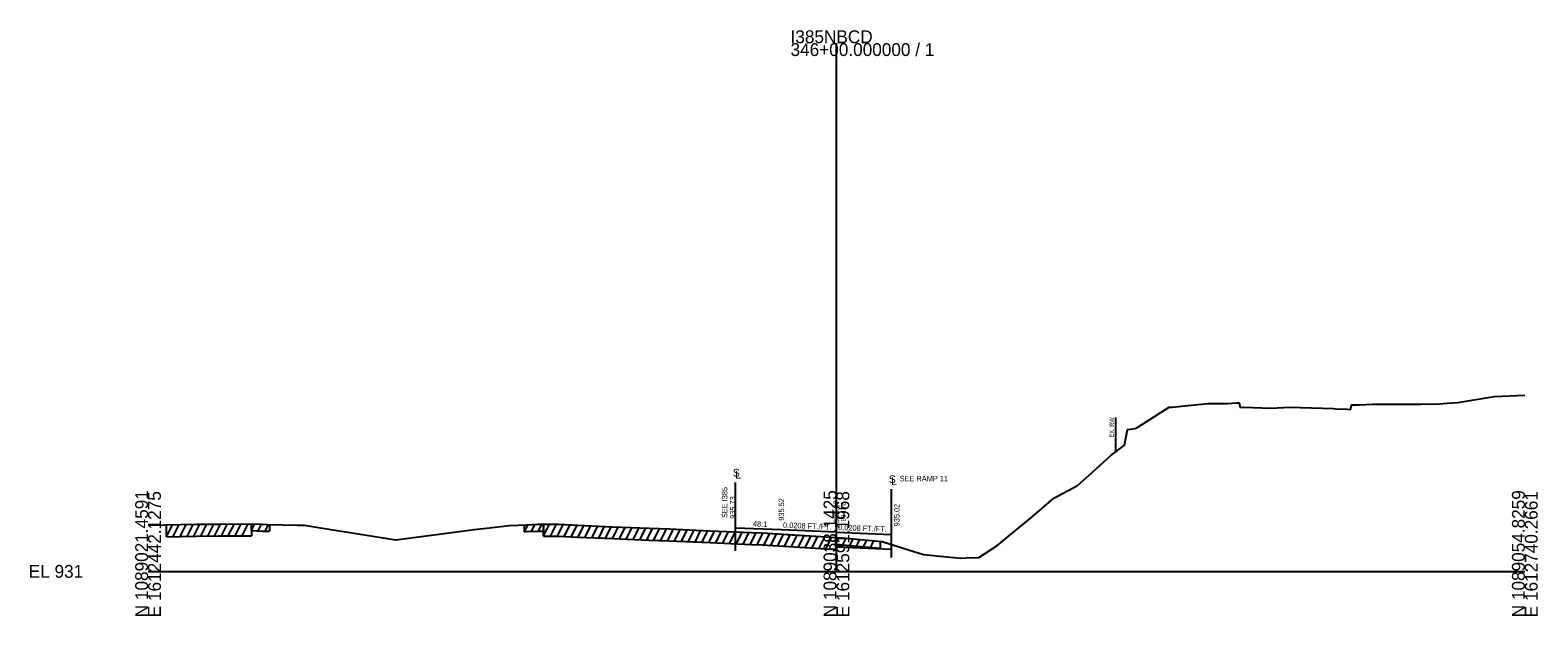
# Model space of a CAD drawing. Extents: x -26 to 1613369, y -10 to 1281970.
# Drawn here: x -25.7 to 302.8, y 16490.3 to 16617.9 of the extents above; entities that cross this region are included whole.
import ezdxf

# ---------------------------------------------------------------- set-up
doc = ezdxf.new("R2010")
doc.units = 0
for name, color, linetype in [('RD_EX_Misc', 7, 'Continuous'), ('RD_GPK_XS_Cell', 7, 'Continuous'), ('RD_Sketch1', 7, 'Continuous'), ('RD_XS_Base', 7, 'Continuous'), ('RD_XS_ExGround', 7, 'Continuous'), ('RD_XS_ExPaveRet', 7, 'Continuous'), ('RD_XS_ExRW', 7, 'Continuous'), ('RD_XS_MatchLine', 7, 'Continuous'), ('RD_XS_Pave', 7, 'Continuous'), ('RD_XS_PaveShd', 7, 'Continuous'), ('RD_XS_TX_Elev_EX', 7, 'Continuous'), ('RD_XS_TX_Elev_PR', 7, 'Continuous'), ('RD_XS_TX_MatchLine', 7, 'Continuous'), ('RD_XS_TX_Notes', 7, 'Continuous'), ('RD_XS_TX_ShdSlope', 7, 'Continuous'), ('RD_XS_TX_Slope', 7, 'Continuous')]:
    doc.layers.add(name, color=color, linetype=linetype)

msp = doc.modelspace()

# ---------------------------------------------------------------- linework, layer by layer
at = {"layer": 'RD_EX_Misc'}
for p, q in [((22.51, 16508.88), (22.51, 16510.38)), ((22.51, 16508.88), (24.87, 16508.78)), ((22.51, 16508.88), (22.51, 16508.88)), ((24.87, 16508.78), (26, 16508.74)), ((26.45, 16510.23), (26.45, 16508.73)), ((82.05, 16508.65), (82.05, 16510.15)), ((82.49, 16508.67), (85, 16508.79)), ((85, 16508.79), (86.2, 16508.78)), ((86.2, 16510.28), (86.2, 16508.78)), ((26, 16508.74), (26.45, 16508.73)), ((82.05, 16508.65), (82.49, 16508.67)), ((149.9, 16505.91), (149.9, 16507.41)), ((149.9, 16505.91), (150, 16505.9)), ((150, 16505.9), (151.35, 16505.78)), ((151.35, 16505.78), (159.53, 16505.03)), ((159.53, 16506.53), (159.53, 16505.03))]:
    msp.add_line(p, q, dxfattribs=at)
at = {"layer": 'RD_GPK_XS_Cell'}
for p, q in [((150, 16500), (150, 16615.11)), ((0, 16500), (150, 16500)), ((150, 16500), (300, 16500))]:
    msp.add_line(p, q, dxfattribs=at)
at = {"layer": 'RD_Sketch1'}
for p, q in [((22.51, 16508.88), (23.25, 16510.35)), ((24.01, 16508.82), (24.75, 16510.29)), ((25.51, 16508.76), (26.25, 16510.24)), ((82.05, 16508.65), (82.81, 16510.18)), ((83.55, 16508.72), (84.31, 16510.25)), ((85.05, 16508.79), (85.79, 16510.28)), ((149.9, 16505.91), (150.62, 16507.35)), ((151.4, 16505.78), (152.12, 16507.21)), ((152.9, 16505.64), (153.62, 16507.07)), ((154.4, 16505.5), (155.12, 16506.94)), ((155.9, 16505.36), (156.62, 16506.8)), ((157.4, 16505.23), (158.12, 16506.66))]:
    msp.add_line(p, q, dxfattribs=at)
at = {"layer": 'RD_XS_Base'}
for p, q in [((128, 16508.62), (131.48, 16508.47)), ((131.48, 16508.47), (133.8, 16508.37)), ((133.8, 16508.37), (138, 16508.12)), ((138, 16508.12), (148.94, 16507.47)), ((148.94, 16507.47), (149.9, 16507.41)), ((149.9, 16505.38), (149.9, 16507.41)), ((162, 16504.87), (162, 16505.86)), ((150, 16505.37), (149.9, 16505.38)), ((150, 16505.37), (162, 16504.87))]:
    msp.add_line(p, q, dxfattribs=at)
at = {"layer": 'RD_XS_ExGround'}
msp.add_lwpolyline([(0, 16510.05), (3.58, 16510.14), (10.5, 16510.26), (15.36, 16510.31), (22.51, 16510.38), (24.87, 16510.28), (26, 16510.24), (32.58, 16510.1), (34.08, 16510.07), (37.55, 16509.52), (54.01, 16506.9), (65.64, 16508.41), (71.04, 16509.1), (73.77, 16509.42), (78.75, 16509.99), (82.49, 16510.17), (85, 16510.29), (87.27, 16510.28), (89.42, 16510.27), (93.62, 16510.08), (101.21, 16509.74), (109.19, 16509.43), (113.57, 16509.25), (122.41, 16508.86), (131.48, 16508.47), (133.8, 16508.37), (148.94, 16507.47), (150, 16507.4), (151.35, 16507.28), (159.93, 16506.5), (165.72, 16504.71), (168.97, 16503.69), (174.02, 16503.17), (177.08, 16502.88), (178.25, 16502.92), (181.06, 16503.05), (184.94, 16505.56), (192.63, 16511.92), (197.37, 16515.99), (202.53, 16518.75), (205.05, 16520.96), (209.78, 16525.26), (212.75, 16527.5), (213.39, 16530.91), (215.1, 16531.16), (215.68, 16531.41), (222.5, 16535.75), (223.15, 16535.8), (226.6, 16536.16), (230.99, 16536.57), (235.25, 16536.59), (237.24, 16536.7), (237.74, 16536.71), (237.99, 16535.71), (238.72, 16535.81), (244.74, 16535.59), (248.71, 16535.81), (258.32, 16535.46), (258.77, 16535.45), (261.39, 16535.38), (262.03, 16535.29), (262.29, 16536.29), (262.79, 16536.29), (263.95, 16536.31), (266.83, 16536.41), (277.4, 16536.42), (281.44, 16536.5), (283.07, 16536.69), (285.4, 16536.79), (293.34, 16538.08), (300, 16538.37)], dxfattribs=at)
at = {"layer": 'RD_XS_ExPaveRet'}
for p, q in [((3.99, 16507.55), (5.3, 16510.17)), ((3.99, 16507.55), (3.99, 16510.15)), ((5.49, 16507.57), (6.8, 16510.19)), ((6.99, 16507.6), (8.3, 16510.22)), ((8.49, 16507.62), (9.8, 16510.24)), ((9.99, 16507.65), (11.3, 16510.26)), ((11.49, 16507.67), (12.8, 16510.28)), ((12.99, 16507.68), (14.3, 16510.3)), ((14.49, 16507.7), (15.8, 16510.32)), ((15.99, 16507.72), (17.3, 16510.33)), ((17.49, 16507.73), (18.8, 16510.34)), ((18.99, 16507.74), (20.3, 16510.36)), ((20.49, 16507.76), (21.8, 16510.37)), ((22.51, 16510.38), (22.51, 16507.78)), ((86.2, 16507.68), (87.5, 16510.28)), ((86.2, 16507.68), (86.2, 16510.28)), ((87.7, 16507.68), (89, 16510.27)), ((89.2, 16507.67), (90.48, 16510.22)), ((90.7, 16507.61), (91.98, 16510.15)), ((92.2, 16507.54), (93.48, 16510.09)), ((93.7, 16507.48), (94.98, 16510.02)), ((95.2, 16507.41), (96.48, 16509.95)), ((96.7, 16507.34), (97.98, 16509.88)), ((98.2, 16507.27), (99.48, 16509.82)), ((99.7, 16507.21), (100.98, 16509.75)), ((101.21, 16507.14), (102.48, 16509.69)), ((102.71, 16507.08), (103.98, 16509.63)), ((104.21, 16507.02), (105.48, 16509.57)), ((105.71, 16506.97), (106.98, 16509.52)), ((107.21, 16506.91), (108.48, 16509.46)), ((108.71, 16506.85), (109.98, 16509.4)), ((110.21, 16506.79), (111.48, 16509.34)), ((111.71, 16506.73), (112.98, 16509.27)), ((113.21, 16506.66), (114.48, 16509.21)), ((114.71, 16506.6), (115.98, 16509.14)), ((116.21, 16506.53), (117.48, 16509.08)), ((117.71, 16506.47), (118.98, 16509.01)), ((119.21, 16506.4), (120.48, 16508.95)), ((120.71, 16506.34), (121.98, 16508.88)), ((122.21, 16506.27), (123.48, 16508.82)), ((3.99, 16507.55), (10.5, 16507.66)), ((10.5, 16507.66), (15.36, 16507.71)), ((15.36, 16507.71), (22.51, 16507.78)), ((86.2, 16507.68), (87.27, 16507.68)), ((87.27, 16507.68), (89.42, 16507.67)), ((89.42, 16507.67), (93.62, 16507.48)), ((93.62, 16507.48), (101.21, 16507.14)), ((101.21, 16507.14), (109.19, 16506.83)), ((109.19, 16506.83), (113.57, 16506.65)), ((113.57, 16506.65), (122.41, 16506.26)), ((122.41, 16506.26), (131.48, 16505.87)), ((123.71, 16506.21), (124.98, 16508.75)), ((125.21, 16506.14), (126.48, 16508.69)), ((126.71, 16506.08), (127.98, 16508.62)), ((128.21, 16506.01), (129.48, 16508.55)), ((129.71, 16505.94), (130.98, 16508.49)), ((131.21, 16505.88), (132.48, 16508.42)), ((131.48, 16505.87), (133.8, 16505.77)), ((132.71, 16505.81), (133.98, 16508.35)), ((133.8, 16505.77), (148.94, 16504.87)), ((134.21, 16505.74), (135.47, 16508.27)), ((135.71, 16505.65), (136.97, 16508.18)), ((137.21, 16505.56), (138.47, 16508.09)), ((138.71, 16505.48), (139.97, 16508)), ((140.21, 16505.39), (141.47, 16507.91)), ((141.71, 16505.3), (142.97, 16507.82)), ((143.21, 16505.21), (144.47, 16507.73)), ((144.71, 16505.12), (145.97, 16507.65)), ((146.21, 16505.03), (147.47, 16507.56)), ((147.71, 16504.94), (148.97, 16507.47)), ((149.9, 16507.41), (149.9, 16504.81)), ((148.94, 16504.87), (149.9, 16504.81))]:
    msp.add_line(p, q, dxfattribs=at)
at = {"layer": 'RD_XS_ExRW'}
msp.add_line((210.81, 16533.56), (210.81, 16526.04), dxfattribs=at)
at = {"layer": 'RD_XS_MatchLine'}
for p, q in [((128, 16508.62), (128, 16509.45)), ((162, 16505.86), (162, 16508.04))]:
    msp.add_line(p, q, dxfattribs=at)
at = {"layer": 'RD_XS_Pave'}
for q in [(138, 16509.04), (162, 16508.04)]:
    msp.add_line((150, 16508.54), q, dxfattribs=at)
at = {"layer": 'RD_XS_PaveShd'}
msp.add_line((138, 16509.04), (128, 16509.45), dxfattribs=at)
at = {"layer": 'RD_XS_TX_MatchLine'}
for p, q in [((128, 16509.45), (128, 16519.34)), ((162, 16508.04), (162, 16517.93)), ((128, 16504.45), (128, 16509.45)), ((162, 16503.04), (162, 16508.04))]:
    msp.add_line(p, q, dxfattribs=at)

# ---------------------------------------------------------------- texts
at = {"layer": 'RD_GPK_XS_Cell'}
for s, p in [('I385NBCD', (140, 16615.11)), ('346+00.000000 / 1', (140, 16612.31)), ('EL 931', (-26, 16498.6))]:
    msp.add_text(s, height=2.8, dxfattribs=at).set_placement(p)
for s, p in [('N 1089021.4591', (0, 16490)), ('E 1612442.1275', (2.8, 16490)), ('N 1089038.1425', (150, 16490)), ('E 1612591.1968', (152.8, 16490)), ('N 1089054.8259', (300, 16490)), ('E 1612740.2661', (302.8, 16490))]:
    msp.add_text(s, height=2.8, rotation=90, dxfattribs=at).set_placement(p)
at = {"layer": 'RD_XS_ExRW'}
msp.add_text('EX. RW', height=0.9, rotation=90, dxfattribs=at).set_placement((210.45, 16529.16))
at = {"layer": 'RD_XS_TX_Elev_EX'}
msp.add_text('934.70', height=1, rotation=90, dxfattribs=at).set_placement((152, 16510.88))
at = {"layer": 'RD_XS_TX_Elev_PR'}
for s, p in [('935.73', (128, 16511.45)), ('935.52', (138.6, 16511.04)), ('935.27', (150.6, 16510.54)), ('935.02', (163.75, 16509.81))]:
    msp.add_text(s, height=1.2, rotation=90, dxfattribs=at).set_placement(p)
at = {"layer": 'RD_XS_TX_MatchLine'}
for s, p in [('S', (127.42, 16520.66)), ('L', (127.93, 16520.22)), ('S', (161.42, 16519.24)), ('L', (161.93, 16518.81))]:
    msp.add_text(s, height=1.68, dxfattribs=at).set_placement(p)
at = {"layer": 'RD_XS_TX_Notes'}
msp.add_text('SEE RAMP 11', height=1.2, dxfattribs=at).set_placement((163.78, 16519.62))
msp.add_text('SEE I385', height=1.2, rotation=90, dxfattribs=at).set_placement((126.23, 16511.62))
at = {"layer": 'RD_XS_TX_ShdSlope'}
msp.add_text('48:1', height=1.2, rotation=357.6141, dxfattribs=at).set_placement((131.79, 16509.8))
at = {"layer": 'RD_XS_TX_Slope'}
for p in [(138.35, 16509.52), (150.35, 16509.02)]:
    msp.add_text('0.0208 FT./FT.', height=1.2, rotation=357.6141, dxfattribs=at).set_placement(p)

doc.saveas('drawing.dxf')
